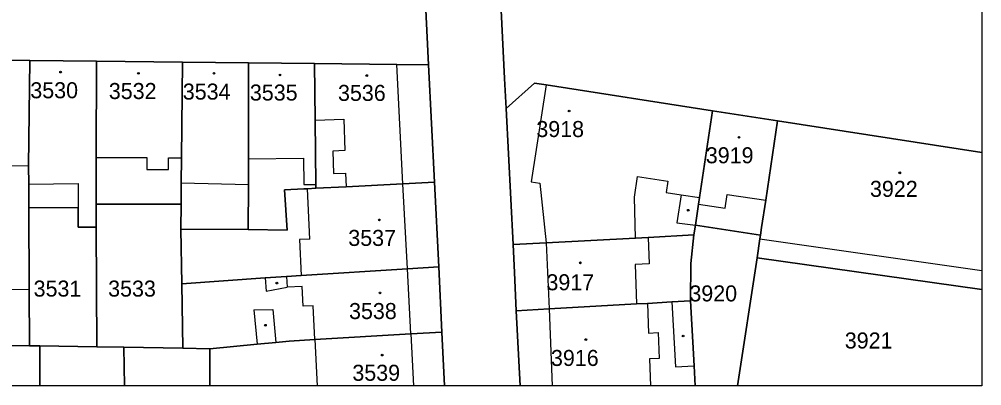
# Model space of a CAD drawing. Extents: x -596233 to -595156, y -1161235 to -1159375.
# Drawn here: x -595260.2 to -595158.2, y -1161235.4 to -1161196.6 of the extents above; entities that cross this region are included whole.
import ezdxf

# ---------------------------------------------------------------- set-up
doc = ezdxf.new("R2010")
doc.units = 0
for name, color, linetype in [('KN_CAR_KR', 7, 'Continuous'), ('KN_KULTURY', 7, 'Continuous'), ('KN_PARC_CIS_POZ', 7, 'Continuous'), ('KN_PARC_CIS_STAV', 7, 'Continuous'), ('KN_PARC_PLOCHA', 7, 'Continuous'), ('parcely_l', 7, 'Continuous')]:
    doc.layers.add(name, color=color, linetype=linetype)

msp = doc.modelspace()

# ---------------------------------------------------------------- linework, layer by layer
at = {"layer": 'KN_CAR_KR'}
for points in [[(-595219.57, -1161214.02), (-595220.23, -1161201.36)], [(-595204.39, -1161203.54), (-595205.98, -1161213.79)], [(-595228.89, -1161207.26), (-595225.85, -1161207.15)], [(-595225.85, -1161207.15), (-595225.73, -1161210.5)], [(-595252.09, -1161211.21), (-595246.72, -1161211.21)], [(-595246.72, -1161211.21), (-595246.72, -1161212.51)], [(-595244.42, -1161212.51), (-595244.42, -1161211.26)], [(-595244.42, -1161211.26), (-595243.05, -1161211.26)], [(-595225.73, -1161210.5), (-595227.01, -1161210.55)], [(-595227.01, -1161210.55), (-595226.93, -1161212.92)], [(-595268.16, -1161211.96), (-595259.25, -1161212.1)], [(-595235.96, -1161211.35), (-595230.11, -1161211.3)], [(-595230.11, -1161211.3), (-595230.08, -1161214.09)], [(-595246.72, -1161212.51), (-595244.42, -1161212.51)], [(-595226.93, -1161212.92), (-595225.65, -1161212.88)], [(-595225.65, -1161212.88), (-595225.6, -1161214.33)], [(-595195.05, -1161215.42), (-595194.71, -1161213.24)], [(-595194.71, -1161213.24), (-595191.49, -1161213.73)], [(-595259.24, -1161214.04), (-595253.99, -1161213.97)], [(-595253.99, -1161213.97), (-595254, -1161216.54)], [(-595243.07, -1161213.92), (-595235.96, -1161214.09)], [(-595230.08, -1161214.09), (-595228.82, -1161214.09)], [(-595219.1, -1161223.02), (-595219.57, -1161214.02)], [(-595205.98, -1161213.79), (-595205.07, -1161213.93)], [(-595205.07, -1161213.93), (-595204.41, -1161220.26)], [(-595191.49, -1161213.73), (-595191.67, -1161214.94)], [(-595229.43, -1161219.87), (-595229.69, -1161214.54)], [(-595191.67, -1161214.94), (-595190.09, -1161215.18)], [(-595190.09, -1161215.18), (-595190.53, -1161218.14)], [(-595190.09, -1161215.18), (-595188.15, -1161215.47)], [(-595185.42, -1161216.59), (-595185.2, -1161215.13)], [(-595185.2, -1161215.13), (-595181.13, -1161215.75)], [(-595194.93, -1161219.76), (-595195.05, -1161215.42)], [(-595188.25, -1161216.16), (-595185.42, -1161216.59)], [(-595190.53, -1161218.14), (-595188.58, -1161218.38)], [(-595229.43, -1161219.87), (-595230.54, -1161219.93)], [(-595230.54, -1161219.93), (-595230.35, -1161223.73)], [(-595204.41, -1161220.26), (-595204.07, -1161227.27)], [(-595193.58, -1161219.69), (-595193.48, -1161222.49)], [(-595181.75, -1161219.83), (-595158.2304, -1161223.213)], [(-595193.48, -1161222.49), (-595194.98, -1161222.55)], [(-595218.74, -1161229.91), (-595219.1, -1161223.02)], [(-595194.98, -1161222.55), (-595194.83, -1161226.75)], [(-595234.18, -1161223.99), (-595234.08, -1161225.39)], [(-595231.91, -1161223.83), (-595231.86, -1161224.97)], [(-595268.25, -1161225.06), (-595259.19, -1161225.2)], [(-595234.08, -1161225.39), (-595231.86, -1161224.97)], [(-595230.25, -1161224.9), (-595231.86, -1161224.97)], [(-595230.14, -1161227), (-595230.25, -1161224.9)], [(-595191.07, -1161226.54), (-595190.69, -1161233.4)], [(-595235.38, -1161227.38), (-595233.37, -1161227.34)], [(-595235.38, -1161227.38), (-595235.03, -1161231.01)], [(-595233.37, -1161227.34), (-595233.04, -1161230.82)], [(-595229.08, -1161226.95), (-595230.14, -1161227)], [(-595228.9, -1161230.52), (-595229.08, -1161226.95)], [(-595204.07, -1161227.27), (-595203.7546, -1161235.4174)], [(-595193.66, -1161226.69), (-595193.55, -1161229.83)], [(-595228.9, -1161230.52), (-595228.6582, -1161235.4174)], [(-595218.74, -1161229.91), (-595218.4539, -1161235.4174)], [(-595193.55, -1161229.83), (-595192.53, -1161229.79)], [(-595192.53, -1161229.79), (-595192.43, -1161232.54)], [(-595192.43, -1161232.54), (-595193.44, -1161232.58)], [(-595193.44, -1161232.58), (-595193.3406, -1161235.4174)], [(-595190.69, -1161233.4), (-595188.72, -1161233.29)]]:
    msp.add_lwpolyline(points, dxfattribs=at)
at = {"layer": 'KN_KULTURY'}
for centre, radius in [((-595255.86, -1161202.18), 0.09), ((-595255.86, -1161202.18), 0.0398), ((-595247.61, -1161202.3), 0.09), ((-595247.61, -1161202.3), 0.0398), ((-595239.6, -1161202.3), 0.09), ((-595239.6, -1161202.3), 0.0398), ((-595232.6, -1161202.48), 0.09), ((-595232.6, -1161202.48), 0.0398), ((-595223.41, -1161202.54), 0.09), ((-595223.41, -1161202.54), 0.0398), ((-595201.96, -1161206.3), 0.09), ((-595201.96, -1161206.3), 0.0398), ((-595183.96, -1161209.09), 0.09), ((-595183.96, -1161209.09), 0.0398), ((-595166.92, -1161212.85), 0.09), ((-595166.92, -1161212.85), 0.0398), ((-595189.34, -1161216.81), 0.09), ((-595189.34, -1161216.81), 0.0398), ((-595222.07, -1161217.84), 0.09), ((-595222.07, -1161217.84), 0.0398), ((-595200.77, -1161222.39), 0.09), ((-595200.77, -1161222.39), 0.0398), ((-595232.93, -1161224.54), 0.09), ((-595232.93, -1161224.54), 0.0398), ((-595222.01, -1161225.58), 0.09), ((-595222.01, -1161225.58), 0.0398), ((-595234.15, -1161229), 0.09), ((-595234.15, -1161229), 0.0398), ((-595200.19, -1161230.52), 0.09), ((-595200.19, -1161230.52), 0.0398), ((-595189.88, -1161230.15), 0.09), ((-595189.88, -1161230.15), 0.0398), ((-595221.77, -1161232.17), 0.09), ((-595221.77, -1161232.17), 0.0398)]:
    msp.add_circle(centre, radius, dxfattribs=at)
at = {"layer": 'KN_PARC_PLOCHA'}
for points in [[(-595266.07, -1161186.08), (-595259.25, -1161186.15), (-595250.3, -1161186.24), (-595249.59, -1161186.25), (-595244.85, -1161186.33), (-595241.85, -1161186.38), (-595238.27, -1161186.43), (-595231.26, -1161186.49), (-595219.56, -1161186.58), (-595217.67, -1161184.62), (-595216.85, -1161201.39), (-595220.23, -1161201.36), (-595228.95, -1161201.27), (-595235.94, -1161201.2), (-595242.95, -1161201.12), (-595252.04, -1161201.03), (-595259.11, -1161200.96), (-595268.11, -1161200.89)], [(-595209.57, -1161187.59), (-595208.8, -1161202.85), (-595208.64, -1161206.05), (-595207.91, -1161220.45), (-595207.76, -1161223.41), (-595207.56, -1161227.47), (-595207.1631, -1161235.4174), (-595215.1538, -1161235.4174), (-595215.44, -1161229.75), (-595215.78, -1161222.83), (-595216.23, -1161213.85), (-595216.85, -1161201.39), (-595217.67, -1161184.62)]]:
    msp.add_lwpolyline(points, dxfattribs=at)
for points in [[(-595190.46, -1161190.55), (-595183.52, -1161191.63), (-595176.6, -1161192.7), (-595164.88, -1161194.49), (-595159.45, -1161195.31), (-595158.2304, -1161195.4961), (-595158.2304, -1161210.7125), (-595179.86, -1161207.35), (-595186.78, -1161206.27), (-595204.39, -1161203.54), (-595205.64, -1161203.34), (-595208.64, -1161206.05), (-595208.8, -1161202.85), (-595209.57, -1161187.59), (-595199.33, -1161189.18), (-595198.14, -1161189.36)], [(-595259.11, -1161200.96), (-595259.25, -1161212.1), (-595259.24, -1161214.04), (-595259.23, -1161216.57), (-595259.19, -1161225.2), (-595259.17, -1161231.2), (-595264.97, -1161231.11), (-595268.29, -1161231.06), (-595268.25, -1161225.06), (-595268.18, -1161214.94), (-595268.16, -1161211.96), (-595268.16, -1161211.04), (-595268.11, -1161200.89)], [(-595252.04, -1161201.03), (-595252.09, -1161211.21), (-595252.1, -1161213.94), (-595252.09, -1161216.16), (-595252.08, -1161218.61), (-595254.01, -1161218.62), (-595254, -1161216.54), (-595259.23, -1161216.57), (-595259.24, -1161214.04), (-595259.25, -1161212.1), (-595259.11, -1161200.96)], [(-595242.95, -1161201.12), (-595243.05, -1161211.26), (-595243.07, -1161213.92), (-595243.08, -1161216.17), (-595252.09, -1161216.16), (-595252.1, -1161213.94), (-595252.09, -1161211.21), (-595252.04, -1161201.03)], [(-595235.94, -1161201.2), (-595235.96, -1161211.35), (-595235.96, -1161214.09), (-595235.97, -1161218.84), (-595243.1, -1161218.83), (-595243.08, -1161216.17), (-595243.07, -1161213.92), (-595243.05, -1161211.26), (-595242.95, -1161201.12)], [(-595228.95, -1161201.27), (-595228.89, -1161207.26), (-595228.82, -1161214.09), (-595228.82, -1161214.49), (-595229.69, -1161214.54), (-595230.08, -1161214.56), (-595232.14, -1161214.66), (-595231.85, -1161218.94), (-595235.97, -1161218.84), (-595235.96, -1161214.09), (-595235.96, -1161211.35), (-595235.94, -1161201.2)], [(-595216.85, -1161201.39), (-595216.23, -1161213.85), (-595219.57, -1161214.02), (-595225.6, -1161214.33), (-595228.82, -1161214.49), (-595228.82, -1161214.09), (-595228.89, -1161207.26), (-595228.95, -1161201.27), (-595220.23, -1161201.36)], [(-595186.78, -1161206.27), (-595188.15, -1161215.47), (-595188.25, -1161216.16), (-595188.58, -1161218.38), (-595188.74, -1161219.43), (-595193.58, -1161219.69), (-595194.93, -1161219.76), (-595204.41, -1161220.26), (-595207.91, -1161220.45), (-595208.64, -1161206.05), (-595205.64, -1161203.34), (-595204.39, -1161203.54)], [(-595179.86, -1161207.35), (-595181.13, -1161215.75), (-595181.57, -1161218.64), (-595181.69, -1161219.46), (-595188.58, -1161218.38), (-595188.25, -1161216.16), (-595188.15, -1161215.47), (-595186.78, -1161206.27)], [(-595158.2304, -1161210.7125), (-595158.2304, -1161225.232), (-595182.05, -1161221.85), (-595181.75, -1161219.83), (-595181.69, -1161219.46), (-595181.57, -1161218.64), (-595181.13, -1161215.75), (-595179.86, -1161207.35)], [(-595215.78, -1161222.83), (-595219.1, -1161223.02), (-595230.35, -1161223.73), (-595231.91, -1161223.83), (-595234.18, -1161223.99), (-595243.01, -1161224.62), (-595243.1, -1161218.83), (-595235.97, -1161218.84), (-595231.85, -1161218.94), (-595232.14, -1161214.66), (-595230.08, -1161214.56), (-595229.69, -1161214.54), (-595228.82, -1161214.49), (-595225.6, -1161214.33), (-595219.57, -1161214.02), (-595216.23, -1161213.85)], [(-595243.08, -1161216.17), (-595243.1, -1161218.83), (-595243.01, -1161224.62), (-595242.9, -1161231.45), (-595249.16, -1161231.34), (-595252.02, -1161231.3), (-595252.08, -1161218.61), (-595252.09, -1161216.16)], [(-595252.08, -1161218.61), (-595252.02, -1161231.3), (-595258.07, -1161231.2), (-595259.17, -1161231.2), (-595259.19, -1161225.2), (-595259.23, -1161216.57), (-595254, -1161216.54), (-595254.01, -1161218.62)], [(-595181.69, -1161219.46), (-595181.75, -1161219.83), (-595182.05, -1161221.85), (-595184.1073, -1161235.4174), (-595188.6018, -1161235.4174), (-595188.72, -1161233.29), (-595189.1, -1161226.43), (-595189.06, -1161222.47), (-595188.74, -1161219.43), (-595188.58, -1161218.38)], [(-595189.1, -1161226.43), (-595191.07, -1161226.54), (-595193.66, -1161226.69), (-595194.83, -1161226.75), (-595204.07, -1161227.27), (-595207.56, -1161227.47), (-595207.76, -1161223.41), (-595207.91, -1161220.45), (-595204.41, -1161220.26), (-595194.93, -1161219.76), (-595193.58, -1161219.69), (-595188.74, -1161219.43), (-595189.06, -1161222.47)], [(-595158.2304, -1161225.232), (-595158.2304, -1161235.4174), (-595184.1073, -1161235.4174), (-595182.05, -1161221.85)], [(-595215.44, -1161229.75), (-595218.74, -1161229.91), (-595228.9, -1161230.52), (-595231.63, -1161230.69), (-595233.04, -1161230.82), (-595235.03, -1161231.01), (-595240.05, -1161231.49), (-595242.9, -1161231.45), (-595243.01, -1161224.62), (-595234.18, -1161223.99), (-595231.91, -1161223.83), (-595230.35, -1161223.73), (-595219.1, -1161223.02), (-595215.78, -1161222.83)], [(-595188.6018, -1161235.4174), (-595207.1631, -1161235.4174), (-595207.56, -1161227.47), (-595204.07, -1161227.27), (-595194.83, -1161226.75), (-595193.66, -1161226.69), (-595191.07, -1161226.54), (-595189.1, -1161226.43), (-595188.72, -1161233.29)], [(-595215.1538, -1161235.4174), (-595240.0384, -1161235.4174), (-595240.05, -1161231.49), (-595235.03, -1161231.01), (-595233.04, -1161230.82), (-595231.63, -1161230.69), (-595228.9, -1161230.52), (-595218.74, -1161229.91), (-595215.44, -1161229.75)], [(-595259.17, -1161231.2), (-595258.07, -1161231.2), (-595258.0438, -1161235.4174), (-595264.9568, -1161235.4174), (-595264.97, -1161231.11)], [(-595252.02, -1161231.3), (-595249.16, -1161231.34), (-595249.0918, -1161235.4174), (-595258.0438, -1161235.4174), (-595258.07, -1161231.2)], [(-595242.9, -1161231.45), (-595240.05, -1161231.49), (-595240.0384, -1161235.4174), (-595249.0918, -1161235.4174), (-595249.16, -1161231.34)]]:
    msp.add_lwpolyline(points, close=True, dxfattribs=at)
at = {"layer": 'parcely_l'}
for points in [[(-595217.67, -1161184.62), (-595216.85, -1161201.39)], [(-595208.64, -1161206.05), (-595208.8, -1161202.85), (-595209.57, -1161187.59)], [(-595158.2304, -1161195.4961), (-595158.2304, -1161210.7125)], [(-595259.11, -1161200.96), (-595268.11, -1161200.89)], [(-595259.11, -1161200.96), (-595259.25, -1161212.1), (-595259.24, -1161214.04), (-595259.23, -1161216.57)], [(-595252.04, -1161201.03), (-595259.11, -1161200.96)], [(-595252.09, -1161216.16), (-595252.1, -1161213.94), (-595252.09, -1161211.21), (-595252.04, -1161201.03)], [(-595242.95, -1161201.12), (-595252.04, -1161201.03)], [(-595243.08, -1161216.17), (-595243.07, -1161213.92), (-595243.05, -1161211.26), (-595242.95, -1161201.12)], [(-595235.94, -1161201.2), (-595242.95, -1161201.12)], [(-595235.94, -1161201.2), (-595235.96, -1161211.35), (-595235.96, -1161214.09), (-595235.97, -1161218.84)], [(-595228.95, -1161201.27), (-595235.94, -1161201.2)], [(-595216.85, -1161201.39), (-595220.23, -1161201.36), (-595228.95, -1161201.27)], [(-595228.82, -1161214.49), (-595228.82, -1161214.09), (-595228.89, -1161207.26), (-595228.95, -1161201.27)], [(-595216.85, -1161201.39), (-595216.23, -1161213.85)], [(-595208.64, -1161206.05), (-595205.64, -1161203.34), (-595204.39, -1161203.54), (-595186.78, -1161206.27)], [(-595207.91, -1161220.45), (-595208.64, -1161206.05)], [(-595186.78, -1161206.27), (-595188.15, -1161215.47), (-595188.25, -1161216.16), (-595188.58, -1161218.38)], [(-595186.78, -1161206.27), (-595179.86, -1161207.35)], [(-595181.69, -1161219.46), (-595181.57, -1161218.64), (-595181.13, -1161215.75), (-595179.86, -1161207.35)], [(-595179.86, -1161207.35), (-595158.2304, -1161210.7125)], [(-595158.2304, -1161210.7125), (-595158.2304, -1161225.232)], [(-595216.23, -1161213.85), (-595219.57, -1161214.02), (-595225.6, -1161214.33), (-595228.82, -1161214.49)], [(-595216.23, -1161213.85), (-595215.78, -1161222.83)], [(-595235.97, -1161218.84), (-595231.85, -1161218.94), (-595232.14, -1161214.66), (-595230.08, -1161214.56), (-595229.69, -1161214.54), (-595228.82, -1161214.49)], [(-595252.08, -1161218.61), (-595252.09, -1161216.16)], [(-595252.09, -1161216.16), (-595243.08, -1161216.17)], [(-595243.08, -1161216.17), (-595243.1, -1161218.83)], [(-595259.23, -1161216.57), (-595254, -1161216.54), (-595254.01, -1161218.62), (-595252.08, -1161218.61)], [(-595259.23, -1161216.57), (-595259.19, -1161225.2), (-595259.17, -1161231.2)], [(-595188.58, -1161218.38), (-595188.74, -1161219.43)], [(-595188.58, -1161218.38), (-595181.69, -1161219.46)], [(-595252.02, -1161231.3), (-595252.08, -1161218.61)], [(-595243.1, -1161218.83), (-595243.01, -1161224.62)], [(-595235.97, -1161218.84), (-595243.1, -1161218.83)], [(-595188.74, -1161219.43), (-595193.58, -1161219.69), (-595194.93, -1161219.76), (-595204.41, -1161220.26), (-595207.91, -1161220.45)], [(-595188.74, -1161219.43), (-595189.06, -1161222.47), (-595189.1, -1161226.43)], [(-595207.56, -1161227.47), (-595207.76, -1161223.41), (-595207.91, -1161220.45)], [(-595182.05, -1161221.85), (-595181.75, -1161219.83), (-595181.69, -1161219.46)], [(-595184.1073, -1161235.4174), (-595182.05, -1161221.85)], [(-595158.2304, -1161225.232), (-595182.05, -1161221.85)], [(-595215.78, -1161222.83), (-595219.1, -1161223.02), (-595230.35, -1161223.73), (-595231.91, -1161223.83), (-595234.18, -1161223.99), (-595243.01, -1161224.62)], [(-595215.78, -1161222.83), (-595215.44, -1161229.75)], [(-595243.01, -1161224.62), (-595242.9, -1161231.45)], [(-595158.2304, -1161225.232), (-595158.2304, -1161235.4174), (-595184.1073, -1161235.4174)], [(-595189.1, -1161226.43), (-595191.07, -1161226.54), (-595193.66, -1161226.69), (-595194.83, -1161226.75), (-595204.07, -1161227.27), (-595207.56, -1161227.47)], [(-595188.6018, -1161235.4174), (-595188.72, -1161233.29), (-595189.1, -1161226.43)], [(-595207.1631, -1161235.4174), (-595207.56, -1161227.47)], [(-595240.05, -1161231.49), (-595235.03, -1161231.01), (-595233.04, -1161230.82), (-595231.63, -1161230.69), (-595228.9, -1161230.52), (-595218.74, -1161229.91), (-595215.44, -1161229.75)], [(-595215.44, -1161229.75), (-595215.1538, -1161235.4174)], [(-595259.17, -1161231.2), (-595264.97, -1161231.11)], [(-595259.17, -1161231.2), (-595258.07, -1161231.2)], [(-595258.07, -1161231.2), (-595258.0438, -1161235.4174)], [(-595252.02, -1161231.3), (-595258.07, -1161231.2)], [(-595249.16, -1161231.34), (-595252.02, -1161231.3)], [(-595242.9, -1161231.45), (-595249.16, -1161231.34)], [(-595249.0918, -1161235.4174), (-595249.16, -1161231.34)], [(-595242.9, -1161231.45), (-595240.05, -1161231.49)], [(-595240.0384, -1161235.4174), (-595240.05, -1161231.49)], [(-595258.0438, -1161235.4174), (-595264.9568, -1161235.4174)], [(-595249.0918, -1161235.4174), (-595258.0438, -1161235.4174)], [(-595240.0384, -1161235.4174), (-595249.0918, -1161235.4174)], [(-595215.1538, -1161235.4174), (-595240.0384, -1161235.4174)], [(-595207.1631, -1161235.4174), (-595215.1538, -1161235.4174)], [(-595188.6018, -1161235.4174), (-595207.1631, -1161235.4174)], [(-595184.1073, -1161235.4174), (-595188.6018, -1161235.4174)]]:
    msp.add_lwpolyline(points, dxfattribs=at)

# ---------------------------------------------------------------- texts
at = {"layer": 'KN_PARC_CIS_POZ'}
for s, p in [('3531', (-595258.7166, -1161225.97)), ('3533', (-595250.8166, -1161225.97)), ('3920', (-595189.2166, -1161226.48)), ('3921', (-595172.7466, -1161231.47))]:
    msp.add_text(s, height=1.7, dxfattribs=at).set_placement(p)
at = {"layer": 'KN_PARC_CIS_STAV'}
for s, p in [('3530', (-595259.0666, -1161204.95)), ('3532', (-595250.7466, -1161205.03)), ('3534', (-595242.9066, -1161205.09)), ('3535', (-595235.7966, -1161205.19)), ('3536', (-595226.4566, -1161205.23)), ('3918', (-595205.4366, -1161209.06)), ('3919', (-595187.4766, -1161211.84)), ('3922', (-595170.0766, -1161215.4)), ('3537', (-595225.3666, -1161220.6)), ('3917', (-595204.3666, -1161225.3)), ('3538', (-595225.2866, -1161228.35)), ('3916', (-595203.8866, -1161233.32)), ('3539', (-595224.9366, -1161234.89))]:
    msp.add_text(s, height=1.7, dxfattribs=at).set_placement(p)

doc.saveas('drawing.dxf')
